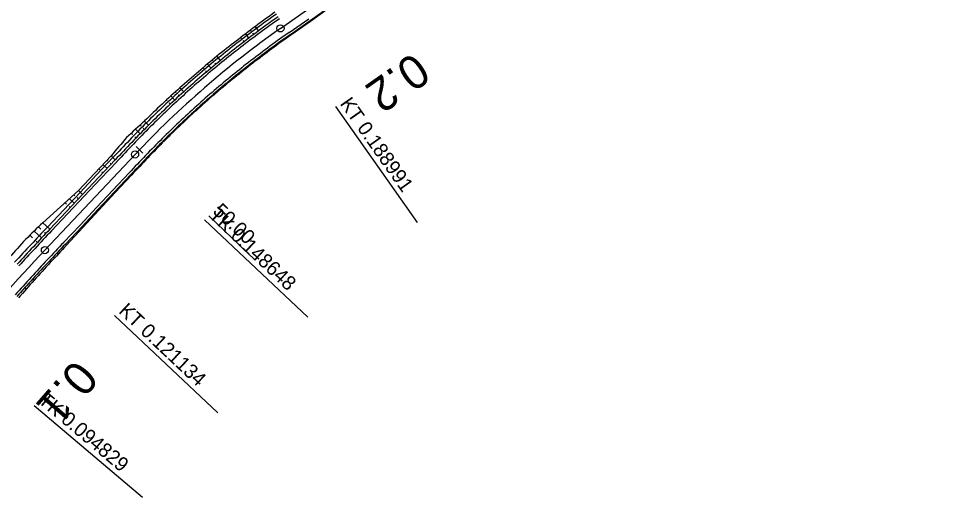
# Model space of a CAD drawing. Extents: x -481645 to -478728, y -1113199 to -1110710.
# Drawn here: x -480517.7 to -480321.2, y -1112921 to -1112820.8 of the extents above; entities that cross this region are included whole.
import ezdxf

# ---------------------------------------------------------------- set-up
doc = ezdxf.new("R2010")
doc.units = 0
for name, color, linetype in [('Vrstva 52', 7, 'Continuous'), ('Vrstva 53', 7, 'Continuous'), ('Vrstva 54', 7, 'Continuous'), ('Vrstva 55', 7, 'Continuous'), ('Vrstva 56', 7, 'Continuous'), ('Vrstva 57', 7, 'Continuous'), ('Vrstva 58', 7, 'Continuous'), ('Vrstva 59', 7, 'Continuous'), ('Vrstva 60', 7, 'Continuous'), ('Vrstva 61', 7, 'Continuous'), ('Vrstva 62', 7, 'Continuous')]:
    doc.layers.add(name, color=color, linetype=linetype)

msp = doc.modelspace()

# ---------------------------------------------------------------- linework, layer by layer
at = {"layer": 'Vrstva 52'}
for p, q in [((-480462.96, -1112822.86), (-480319.49, -1112721.76)), ((-480512.23, -1112869.29), (-480493.37, -1112849.26))]:
    msp.add_line(p, q, dxfattribs=at)
for centre, radius, start, end in [((-480347.75, -1112986.35), 200, 125.1722, 136.7297), ((-480148.17, -1113212.01), 500, 136.7297, 139.744)]:
    msp.add_arc(centre, radius, start, end, dxfattribs=at)
at = {"layer": 'Vrstva 53'}
for p, q in [((-480456.68, -1112821.34), (-480452.61, -1112818.43)), ((-480460.75, -1112824.24), (-480456.68, -1112821.34)), ((-480501.79, -1112853.21), (-480498.38, -1112849.56)), ((-480505.24, -1112856.83), (-480501.79, -1112853.21)), ((-480497.51, -1112857.24), (-480494.1, -1112853.59)), ((-480508.94, -1112860.21), (-480505.24, -1112856.83)), ((-480500.92, -1112860.9), (-480497.51, -1112857.24)), ((-480512.69, -1112863.55), (-480508.94, -1112860.21)), ((-480504.32, -1112864.57), (-480500.92, -1112860.9)), ((-480507.71, -1112868.24), (-480504.32, -1112864.57))]:
    msp.add_line(p, q, dxfattribs=at)
for centre, radius, start, end in [((-480406.48, -1112903.28), 101.69, 124.5115, 127.367), ((-480346.31, -1112985.25), 203.37, 126.8231, 128.2556), ((-480349.3, -1112987.56), 203.37, 127.1932, 128.6257), ((-480404.73, -1112905.61), 98.78, 124.5477, 127.42), ((-480348.06, -1112986.58), 197.57, 126.2011, 127.6335), ((-480346.09, -1112984.94), 203.37, 129.7928, 131.2253), ((-480348.01, -1112986.56), 197.58, 127.6494, 129.0818), ((-480350.02, -1112988.32), 203.38, 129.7653, 131.1978), ((-480347.98, -1112986.54), 197.59, 129.0916, 130.524), ((-480348.62, -1112987.15), 203.43, 131.7096, 133.1421), ((-480347.99, -1112986.56), 197.6, 130.5197, 131.9521), ((-480348.03, -1112986.62), 203.45, 133.3653, 134.7977), ((-480347.78, -1112986.38), 197.6, 132.0319, 133.4642), ((-480355.78, -1112994.12), 203.59, 131.7635, 133.1981), ((-480347.31, -1112985.92), 197.6, 133.6544, 135.0868), ((-480028.2, -1113240.06), 611.2, 139.81695, 140.28883), ((-480347.32, -1112985.91), 197.58, 135.0878, 136.5202), ((-480059.94, -1113257.1), 592.72, 136.6137, 137.09544), ((-480338.31, -1113045.81), 252.24, 133.7342, 134.8733), ((-480143.94, -1113207.39), 504.45, 137.5711, 138.1441), ((-480326.88, -1113038.97), 248.69, 136.646, 137.7966), ((-480145.35, -1113208.95), 497.37, 137.3384, 137.9114), ((-480145.33, -1113208.87), 497.33, 137.9203, 138.4933)]:
    msp.add_arc(centre, radius, start, end, dxfattribs=at)
at = {"layer": 'Vrstva 54'}
for p, q in [((-480501.42, -1112853.55), (-480498, -1112849.92)), ((-480504.85, -1112857.2), (-480501.42, -1112853.55)), ((-480508.28, -1112860.84), (-480504.85, -1112857.2)), ((-480511.71, -1112864.48), (-480508.28, -1112860.84))]:
    msp.add_line(p, q, dxfattribs=at)
for centre, radius, start, end in [((-480406.78, -1112903.81), 101.46, 124.2014, 127.0582), ((-480347.75, -1112986.35), 202.92, 126.3155, 127.7479), ((-480347.75, -1112986.35), 202.92, 127.7479, 129.1803), ((-480347.75, -1112986.35), 202.92, 129.1803, 130.6127), ((-480347.75, -1112986.35), 202.92, 130.6127, 132.0451), ((-480347.75, -1112986.35), 202.92, 132.0451, 133.4775), ((-480347.75, -1112986.35), 202.92, 133.4775, 134.9099), ((-480347.75, -1112986.35), 202.92, 134.9099, 136.3423), ((-480053.42, -1113265.76), 608.75, 136.4405, 136.91296), ((-480330.29, -1113038.6), 251.46, 136.174, 137.3148), ((-480148.17, -1113212.01), 502.92, 136.8596, 137.4326)]:
    msp.add_arc(centre, radius, start, end, dxfattribs=at)
at = {"layer": 'Vrstva 55'}
for p, q in [((-480456.75, -1112821.24), (-480452.66, -1112818.36)), ((-480460.83, -1112824.12), (-480456.75, -1112821.24)), ((-480500.94, -1112854.01), (-480497.51, -1112850.37)), ((-480504.37, -1112857.65), (-480500.94, -1112854.01)), ((-480497.66, -1112857.1), (-480494.24, -1112853.46)), ((-480507.79, -1112861.29), (-480504.37, -1112857.65)), ((-480501.09, -1112860.74), (-480497.66, -1112857.1)), ((-480504.52, -1112864.38), (-480501.09, -1112860.74)), ((-480511.22, -1112864.93), (-480507.79, -1112861.29)), ((-480507.94, -1112868.02), (-480504.52, -1112864.38))]:
    msp.add_line(p, q, dxfattribs=at)
for centre, radius, start, end in [((-480406.59, -1112904.08), 101.12, 124.2002, 127.0588), ((-480347.75, -1112986.35), 202.25, 126.3155, 127.7479), ((-480405.27, -1112905.9), 98.88, 124.1916, 127.0632), ((-480347.75, -1112986.35), 202.25, 127.7479, 129.1803), ((-480347.75, -1112986.35), 197.75, 126.3155, 127.7479), ((-480347.75, -1112986.35), 202.25, 129.1803, 130.6127), ((-480347.75, -1112986.35), 197.75, 127.7479, 129.1803), ((-480347.75, -1112986.35), 202.25, 130.6127, 132.0451), ((-480347.75, -1112986.35), 197.75, 129.1803, 130.6127), ((-480347.75, -1112986.35), 202.25, 132.0451, 133.4775), ((-480347.75, -1112986.35), 197.75, 130.6127, 132.0451), ((-480347.75, -1112986.35), 202.25, 133.4775, 134.9099), ((-480347.75, -1112986.35), 197.75, 132.0451, 133.4775), ((-480347.75, -1112986.35), 202.25, 134.9099, 136.3423), ((-480347.75, -1112986.35), 197.75, 133.4775, 134.9099), ((-480054.39, -1113264.84), 606.75, 136.44006, 136.91365), ((-480347.75, -1112986.35), 197.75, 134.9099, 136.3423), ((-480060.94, -1113258.67), 593.25, 136.437, 136.91843), ((-480330.05, -1113038.83), 251.12, 136.1734, 137.3154), ((-480148.17, -1113212.01), 502.25, 136.8596, 137.4326), ((-480328.41, -1113040.37), 248.88, 136.1694, 137.3193), ((-480148.17, -1113212.01), 497.75, 136.8596, 137.4326), ((-480148.17, -1113212.01), 497.75, 137.4326, 138.0055)]:
    msp.add_arc(centre, radius, start, end, dxfattribs=at)
at = {"layer": 'Vrstva 56'}
for p, q in [((-480461.12, -1112823.71), (-480457.04, -1112820.83)), ((-480500.58, -1112854.35), (-480497.15, -1112850.71)), ((-480498.03, -1112856.75), (-480494.6, -1112853.11)), ((-480504, -1112858), (-480500.58, -1112854.35)), ((-480501.45, -1112860.39), (-480498.03, -1112856.75)), ((-480507.43, -1112861.64), (-480504, -1112858)), ((-480504.88, -1112864.03), (-480501.45, -1112860.39)), ((-480510.86, -1112865.28), (-480507.43, -1112861.64)), ((-480508.31, -1112867.68), (-480504.88, -1112864.03))]:
    msp.add_line(p, q, dxfattribs=at)
for centre, radius, start, end in [((-480406.44, -1112904.28), 100.88, 124.1993, 127.0593), ((-480347.75, -1112986.35), 201.75, 126.3155, 127.7479), ((-480405.42, -1112905.7), 99.13, 124.1926, 127.0627), ((-480347.75, -1112986.35), 201.75, 127.7479, 129.1803), ((-480347.75, -1112986.35), 198.25, 126.3155, 127.7479), ((-480347.75, -1112986.35), 201.75, 129.1803, 130.6127), ((-480347.75, -1112986.35), 198.25, 127.7479, 129.1803), ((-480347.75, -1112986.35), 201.75, 130.6127, 132.0451), ((-480347.75, -1112986.35), 198.25, 129.1803, 130.6127), ((-480347.75, -1112986.35), 201.75, 132.0451, 133.4775), ((-480347.75, -1112986.35), 198.25, 130.6127, 132.0451), ((-480347.75, -1112986.35), 198.25, 132.0451, 133.4775), ((-480347.75, -1112986.35), 201.75, 133.4775, 134.9099), ((-480347.75, -1112986.35), 198.25, 133.4775, 134.9099), ((-480347.75, -1112986.35), 201.75, 134.9099, 136.3423), ((-480055.12, -1113264.16), 605.25, 136.43973, 136.91417), ((-480347.75, -1112986.35), 198.25, 134.9099, 136.3423), ((-480060.21, -1113259.35), 594.75, 136.43735, 136.91789), ((-480329.87, -1113039), 250.88, 136.173, 137.3158), ((-480328.59, -1113040.2), 249.12, 136.1698, 137.3189), ((-480148.17, -1113212.01), 501.75, 136.8596, 137.4326), ((-480148.17, -1113212.01), 498.25, 136.8596, 137.4326), ((-480148.17, -1113212.01), 498.25, 137.4326, 138.0055)]:
    msp.add_arc(centre, radius, start, end, dxfattribs=at)
at = {"layer": 'Vrstva 57'}
for p, q in [((-480461.12, -1112823.71), (-480457.04, -1112820.83)), ((-480500.58, -1112854.35), (-480497.15, -1112850.71)), ((-480498.03, -1112856.75), (-480494.6, -1112853.11)), ((-480504, -1112858), (-480500.58, -1112854.35)), ((-480501.45, -1112860.39), (-480498.03, -1112856.75)), ((-480507.43, -1112861.64), (-480504, -1112858)), ((-480504.88, -1112864.03), (-480501.45, -1112860.39)), ((-480510.86, -1112865.28), (-480507.43, -1112861.64)), ((-480508.31, -1112867.68), (-480504.88, -1112864.03))]:
    msp.add_line(p, q, dxfattribs=at)
for centre, radius, start, end in [((-480406.44, -1112904.28), 100.88, 124.1993, 127.0593), ((-480347.75, -1112986.35), 201.75, 126.3155, 127.7479), ((-480405.42, -1112905.7), 99.13, 124.1926, 127.0627), ((-480347.75, -1112986.35), 201.75, 127.7479, 129.1803), ((-480347.75, -1112986.35), 198.25, 126.3155, 127.7479), ((-480347.75, -1112986.35), 201.75, 129.1803, 130.6127), ((-480347.75, -1112986.35), 198.25, 127.7479, 129.1803), ((-480347.75, -1112986.35), 201.75, 130.6127, 132.0451), ((-480347.75, -1112986.35), 198.25, 129.1803, 130.6127), ((-480347.75, -1112986.35), 201.75, 132.0451, 133.4775), ((-480347.75, -1112986.35), 198.25, 130.6127, 132.0451), ((-480347.75, -1112986.35), 198.25, 132.0451, 133.4775), ((-480347.75, -1112986.35), 201.75, 133.4775, 134.9099), ((-480347.75, -1112986.35), 198.25, 133.4775, 134.9099), ((-480347.75, -1112986.35), 201.75, 134.9099, 136.3423), ((-480055.12, -1113264.16), 605.25, 136.43973, 136.91417), ((-480347.75, -1112986.35), 198.25, 134.9099, 136.3423), ((-480060.21, -1113259.35), 594.75, 136.43735, 136.91789), ((-480329.87, -1113039), 250.88, 136.173, 137.3158), ((-480328.59, -1113040.2), 249.12, 136.1698, 137.3189), ((-480148.17, -1113212.01), 501.75, 136.8596, 137.4326), ((-480148.17, -1113212.01), 498.25, 136.8596, 137.4326), ((-480148.17, -1113212.01), 498.25, 137.4326, 138.0055)]:
    msp.add_arc(centre, radius, start, end, dxfattribs=at)
at = {"layer": 'Vrstva 58'}
for p, q in [((-480491.72, -1112848.97), (-480493.17, -1112847.59)), ((-480477.97, -1112862.08), (-480468.21, -1112871.4))]:
    msp.add_line(p, q, dxfattribs=at)
at = {"layer": 'Vrstva 59'}
for p, q in [((-480451.43, -1112839.21), (-480434.33, -1112863.49)), ((-480478.81, -1112862.97), (-480457.19, -1112883.32)), ((-480497.67, -1112883), (-480476.04, -1112903.36)), ((-480514.49, -1112901.83), (-480491.82, -1112921.03))]:
    msp.add_line(p, q, dxfattribs=at)
for centre in [(-480462.96, -1112822.86), (-480493.37, -1112849.26), (-480512.23, -1112869.29)]:
    msp.add_circle(centre, 0.75, dxfattribs=at)
at = {"layer": 'Vrstva 61'}
for p, q in [((-480469.08, -1112823.41), (-480469.22, -1112823.23)), ((-480467.53, -1112823.38), (-480468.2, -1112822.46)), ((-480471.1, -1112824.95), (-480471.23, -1112824.78)), ((-480470.56, -1112825.65), (-480470.76, -1112825.39)), ((-480469.55, -1112824.89), (-480470.23, -1112824)), ((-480468.54, -1112824.13), (-480468.74, -1112823.86)), ((-480477.07, -1112829.68), (-480477.22, -1112829.5)), ((-480475.52, -1112829.57), (-480476.24, -1112828.68)), ((-480479.01, -1112831.32), (-480479.15, -1112831.15)), ((-480477.47, -1112831.18), (-480478.19, -1112830.32)), ((-480476.5, -1112830.37), (-480476.71, -1112830.11)), ((-480478.44, -1112831.99), (-480478.65, -1112831.74)), ((-480483.2, -1112836.15), (-480483.98, -1112835.29)), ((-480485.07, -1112837.86), (-480485.86, -1112836.99)), ((-480484.75, -1112836.32), (-480484.92, -1112836.14)), ((-480484.13, -1112837), (-480484.36, -1112836.76)), ((-480486.62, -1112838.04), (-480486.8, -1112837.85)), ((-480485.99, -1112838.72), (-480486.22, -1112838.47)), ((-480492.12, -1112843.32), (-480492.33, -1112843.11)), ((-480490.54, -1112843.11), (-480491.39, -1112842.26)), ((-480493.94, -1112845.09), (-480494.21, -1112844.83)), ((-480492.32, -1112844.91), (-480493.28, -1112843.97)), ((-480491.43, -1112844), (-480491.66, -1112843.77)), ((-480493.2, -1112845.81), (-480493.44, -1112845.58)), ((-480499.04, -1112850.65), (-480499.23, -1112850.47)), ((-480498.37, -1112851.28), (-480498.61, -1112851.05)), ((-480497.51, -1112850.37), (-480498.38, -1112849.56)), ((-480500.75, -1112852.47), (-480500.93, -1112852.3)), ((-480500.08, -1112853.1), (-480500.33, -1112852.87)), ((-480499.23, -1112852.19), (-480500.08, -1112851.39)), ((-480504.37, -1112857.65), (-480505.24, -1112856.83)), ((-480506.08, -1112859.47), (-480507.09, -1112858.52)), ((-480505.94, -1112857.89), (-480506.16, -1112857.68)), ((-480505.22, -1112858.56), (-480505.47, -1112858.33)), ((-480507.72, -1112859.65), (-480508.02, -1112859.37)), ((-480506.94, -1112860.38), (-480507.18, -1112860.15)), ((-480513.07, -1112864.91), (-480513.58, -1112864.43)), ((-480511.22, -1112864.93), (-480512.69, -1112863.55)), ((-480514.83, -1112866.69), (-480515.38, -1112866.17)), ((-480512.93, -1112866.75), (-480514.48, -1112865.3)), ((-480512.08, -1112865.84), (-480512.32, -1112865.62)), ((-480513.79, -1112867.66), (-480514.03, -1112867.44))]:
    msp.add_line(p, q, dxfattribs=at)
at = {"layer": 'Vrstva 62'}
for p, q in [((-480456.75, -1112821.24), (-480456.68, -1112821.34)), ((-480459.81, -1112823.4), (-480459.77, -1112823.46)), ((-480459.73, -1112823.52), (-480459.73, -1112823.52)), ((-480458.79, -1112822.68), (-480458.71, -1112822.79)), ((-480457.77, -1112821.96), (-480457.73, -1112822.01)), ((-480457.7, -1112822.06), (-480457.7, -1112822.06)), ((-480464.86, -1112827.01), (-480464.75, -1112827.15)), ((-480467.83, -1112829.23), (-480467.78, -1112829.3)), ((-480467.72, -1112829.37), (-480467.72, -1112829.37)), ((-480466.84, -1112828.48), (-480466.74, -1112828.62)), ((-480465.85, -1112827.74), (-480465.8, -1112827.81)), ((-480465.75, -1112827.89), (-480465.75, -1112827.89)), ((-480472.68, -1112833.06), (-480472.58, -1112833.19)), ((-480475.53, -1112835.43), (-480475.48, -1112835.49)), ((-480474.59, -1112834.63), (-480474.48, -1112834.75)), ((-480473.64, -1112833.84), (-480473.58, -1112833.9)), ((-480473.53, -1112833.97), (-480473.53, -1112833.97)), ((-480475.43, -1112835.55), (-480475.43, -1112835.55)), ((-480482.01, -1112841.16), (-480481.91, -1112841.27)), ((-480481.1, -1112840.32), (-480481.05, -1112840.38)), ((-480481, -1112840.43), (-480481, -1112840.43)), ((-480480.18, -1112839.49), (-480480.09, -1112839.6)), ((-480482.91, -1112842), (-480482.86, -1112842.06)), ((-480482.81, -1112842.11), (-480482.81, -1112842.11)), ((-480488.23, -1112847.17), (-480488.17, -1112847.23)), ((-480487.36, -1112846.3), (-480487.24, -1112846.41)), ((-480489.96, -1112848.94), (-480489.9, -1112849)), ((-480489.83, -1112849.06), (-480489.83, -1112849.06)), ((-480489.1, -1112848.05), (-480488.98, -1112848.17)), ((-480488.11, -1112847.29), (-480488.11, -1112847.29)), ((-480495.09, -1112854.37), (-480495.02, -1112854.43)), ((-480494.95, -1112854.5), (-480494.95, -1112854.5)), ((-480494.24, -1112853.46), (-480494.1, -1112853.59)), ((-480496.81, -1112856.19), (-480496.73, -1112856.26)), ((-480496.66, -1112856.33), (-480496.66, -1112856.33)), ((-480495.95, -1112855.28), (-480495.8, -1112855.41)), ((-480501.09, -1112860.74), (-480500.92, -1112860.9)), ((-480502.8, -1112862.56), (-480502.62, -1112862.73)), ((-480501.95, -1112861.65), (-480501.86, -1112861.73)), ((-480501.77, -1112861.82), (-480501.77, -1112861.82)), ((-480503.66, -1112863.47), (-480503.56, -1112863.56)), ((-480503.47, -1112863.65), (-480503.47, -1112863.65)), ((-480507.94, -1112868.02), (-480507.71, -1112868.24)), ((-480510.52, -1112870.75), (-480510.39, -1112870.87)), ((-480509.66, -1112869.84), (-480509.41, -1112870.07)), ((-480508.8, -1112868.93), (-480508.68, -1112869.04)), ((-480508.56, -1112869.16), (-480508.56, -1112869.16)), ((-480510.26, -1112870.99), (-480510.26, -1112870.99)), ((-480515.59, -1112876.22), (-480515.44, -1112876.36)), ((-480515.29, -1112876.5), (-480515.29, -1112876.5)), ((-480514.75, -1112875.3), (-480514.46, -1112875.58)), ((-480517.27, -1112878.06), (-480517.11, -1112878.21)), ((-480516.95, -1112878.36), (-480516.95, -1112878.36)), ((-480516.43, -1112877.14), (-480516.12, -1112877.43))]:
    msp.add_line(p, q, dxfattribs=at)

# ---------------------------------------------------------------- texts
at = {"layer": 'Vrstva 58'}
msp.add_text('50.00', height=2.999, rotation=316.3423, dxfattribs=at).set_placement((-480477.28, -1112861.36))
at = {"layer": 'Vrstva 59'}
for s, rotation, p in [('KT 0.188991', 305.1722, (-480450.62, -1112838.63)), ('TK 0.148648', 316.7297, (-480478.13, -1112862.24)), ('KT 0.121134', 316.7297, (-480496.98, -1112882.27)), ('TK 0.094829', 319.744, (-480513.84, -1112901.07))]:
    msp.add_text(s, height=2.999, rotation=rotation, dxfattribs=at).set_placement(p)
at = {"layer": 'Vrstva 60'}
for s, height, rotation, p in [('0.2', 7, 215.1265, (-480435.04, -1112827.67)), ('0.1', 6.999, 229.1058, (-480505.91, -1112891.89))]:
    msp.add_text(s, height=height, rotation=rotation, dxfattribs=at).set_placement(p)

doc.saveas('drawing.dxf')
